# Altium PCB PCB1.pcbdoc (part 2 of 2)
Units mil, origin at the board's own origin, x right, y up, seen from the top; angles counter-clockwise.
Board outline 1771.65 x 1825.33 mil, 2 copper layers (Top Layer, Bottom Layer), stack 62.206 mil thick; 72 components, 46 nets, 229 pads, 305 vias.
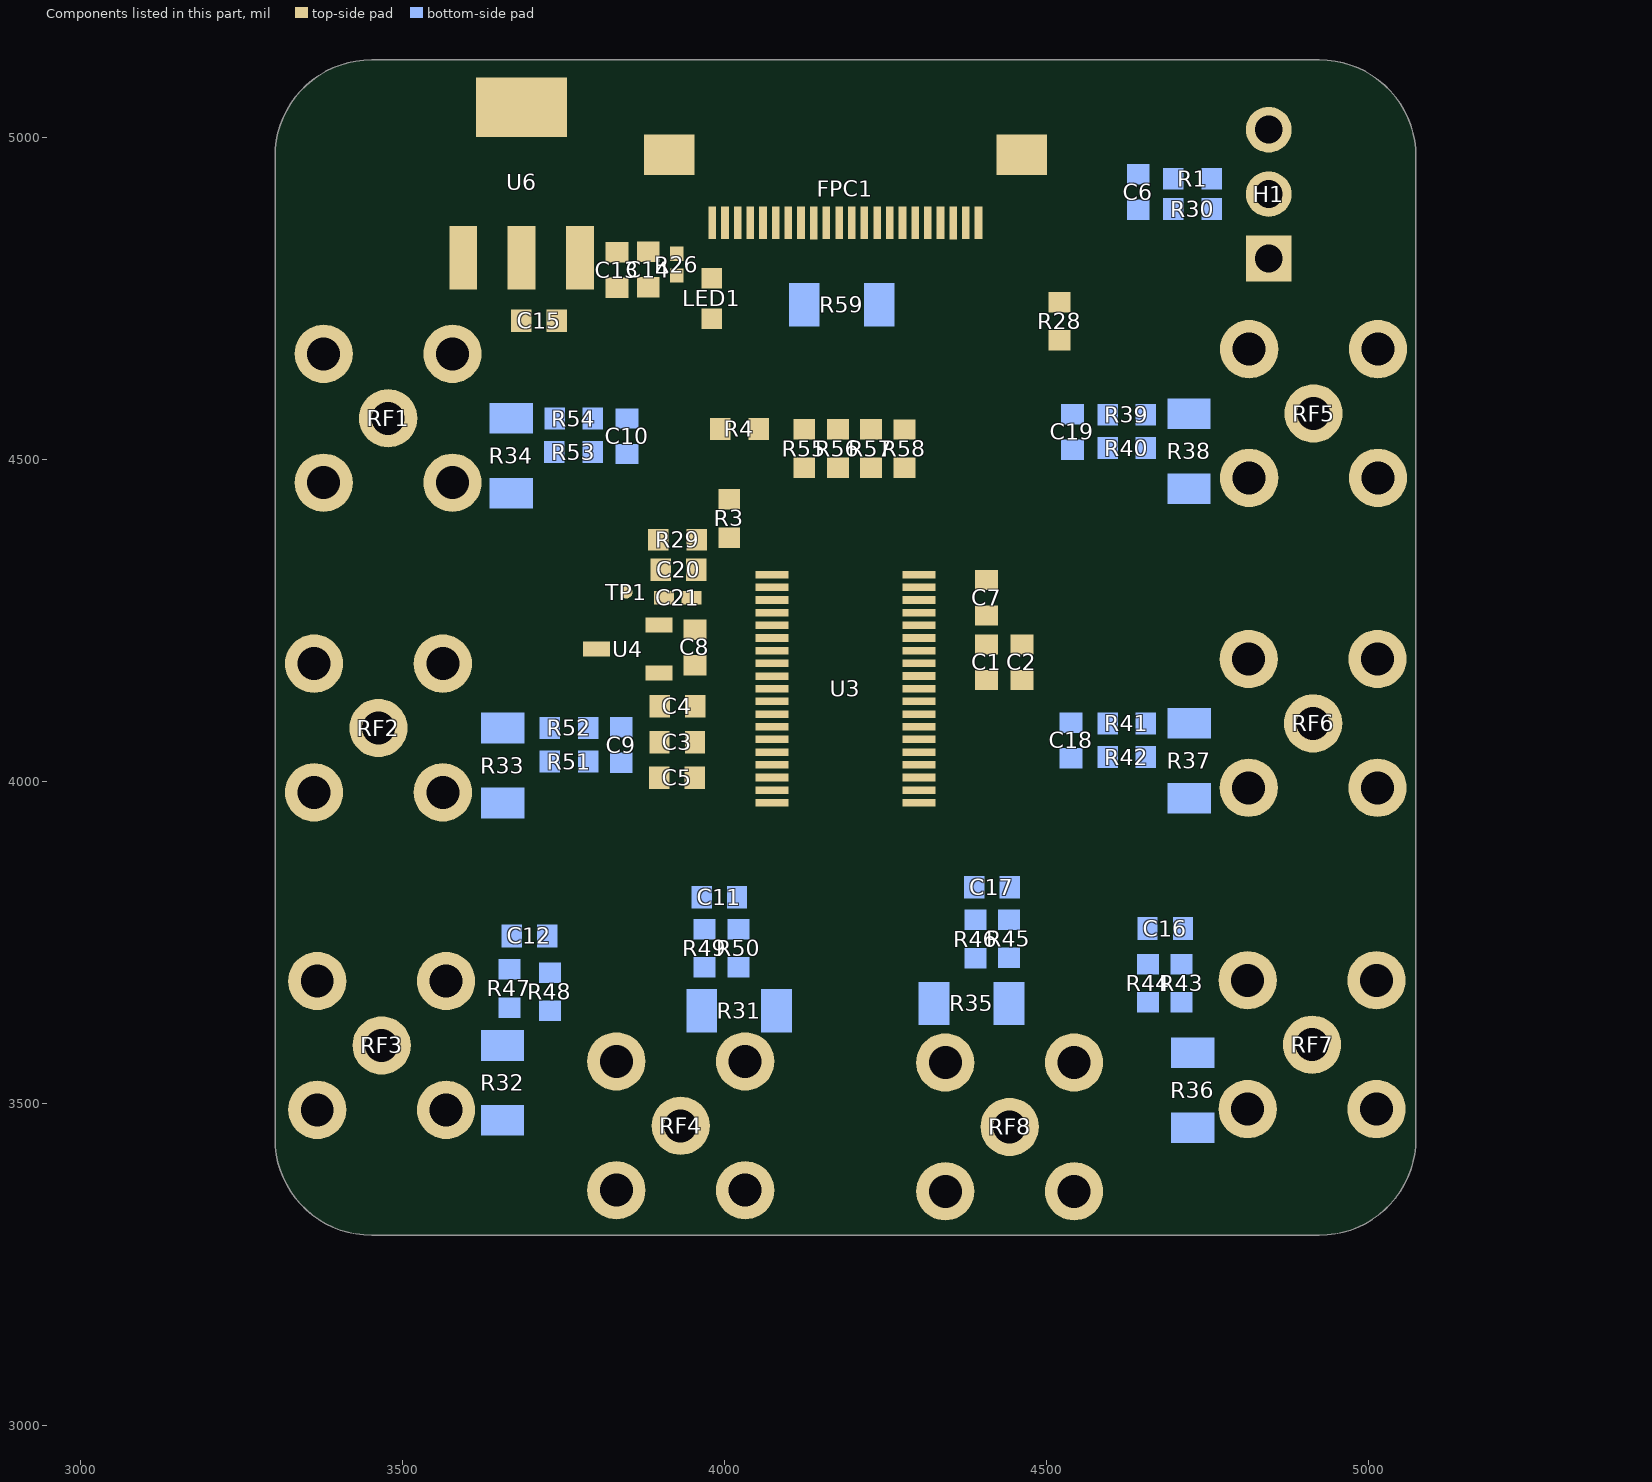
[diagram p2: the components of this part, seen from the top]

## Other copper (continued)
Bottom Layer:
  region net $1N11929: 4621.6,4901.16 4628.74,4908.17 ccw(c4644.65,4929.38) 4644.65,4902.86 4625,4887.15 ccw(c4594.43,4887.15)
  region net $1N11847: 4628.74,4921.18 4621.64,4928.23 ccw(c4594.3,4942.2) 4625,4942.2 4644.65,4926.49 ccw(c4644.65,4899.97)
  region net $1N2508: 3872.77,4088.48 3872.77,4078.48 ccw(c3872.77,4059.73) 3857.77,4070.98 3857.77,4095.98 ccw(c3872.77,4107.23)
  region net $1N2515: 3872.77,4033.36 3872.77,4023.36 ccw(c3872.77,4004.61) 3857.77,4015.86 3857.77,4040.86 ccw(c3872.77,4052.11)
  region net $1N2496: 3872.01,4542.7 3858.57,4542 ccw(c3842.66,4520.79) 3842.66,4547.3 3866.71,4558.61 ccw(c3893.23,4558.61)
  region net $1N2502: 3872.01,4491.98 3862.97,4486.88 ccw(c3847.06,4465.67) 3847.06,4492.18 3866.71,4507.89 ccw(c3893.23,4507.89)
  region net $1N2534: 3975.1,3852.41 3985.1,3852.41 ccw(c4007.52,3837.41) 3980.55,3837.41 3967.6,3837.41 ccw(c3956.35,3852.41)
  region net $1N2549: 4019.61,3852.41 4029.61,3852.41 ccw(c4051.2,3852.41) 4035.67,3837.41 4012.11,3837.41 ccw(c4000.86,3852.41)
  region net $1N2525: 3664.8,3792.41 3674.8,3792.41 ccw(c3693.55,3792.41) 3682.3,3777.41 3657.3,3777.41 ccw(c3646.05,3792.41)
  region net $1N2541: 3755.67,3764.69 3755.67,3754.69 ccw(c3755.67,3735.94) 3740.67,3747.19 3740.67,3772.19 ccw(c3755.67,3783.44)
  region net $1N3142: 4636.23,3770.32 4626.27,3794.42 ccw(c4640.37,3808.52) 4641.53,3788.61 4641.53,3754.41 ccw(c4615.01,3754.41)
  region net $1N3136: 4687.95,3801.13 4706.72,3796.51 ccw(c4728.8,3818.58) 4720.04,3788.61 4696.65,3788.61 ccw(c4657.51,3770.68)
  region net $1N3155: 4382.99,3867.85 4392.99,3867.85 ccw(c4411.74,3867.85) 4400.49,3852.85 4375.49,3852.85 ccw(c4364.24,3867.85)
  region net $1N3148: 4438.53,3867.85 4448.53,3867.85 ccw(c4467.28,3867.85) 4456.03,3852.85 4431.03,3852.85 ccw(c4419.78,3867.85)
  region net $1N17239: 4505.89,4035.09 4505.89,4045.09 ccw(c4505.89,4066.18) 4520.89,4051.36 4520.89,4027.59 ccw(c4505.89,4016.34)
  region net $1N17244: 4505.89,4070.09 4505.89,4080.09 ccw(c4505.89,4098.84) 4520.89,4087.59 4520.89,4074.98 ccw(c4520.89,4049.53)
  region net $1N3111: 4545.63,4483.8 4535.63,4483.8 ccw(c4516.88,4483.8) 4528.13,4498.8 4553.13,4498.8 ccw(c4564.38,4483.8)
  region net $1N3102: 4512.34,4564.67 4512.34,4574.67 ccw(c4512.34,4585.88) 4522.92,4582.17 4522.92,4557.17 ccw(c4512.34,4553.46)
  region net AUX: 4803.6,4844.83 4812.09,4853.31 ccw(c4831.18,4878.77) 4831.18,4846.95 4809.96,4825.74 ccw(c4778.14,4825.74)
  region net AUX: 4779.21,4886.19 4787.73,4860.7 ccw(c4752.44,4825.41) 4772.63,4871.05 4772.63,4905.07 ccw(c4802.99,4905.07)
  region net $1N3616: 3975.64,3591.86 3963.64,3591.86 ccw(c3941.14,3591.86) 3954.64,3609.86 3984.64,3609.86 ccw(c3998.14,3591.86)
  region net $1N3593: 3604.36,3583.52 3604.36,3595.52 ccw(c3604.36,3618.02) 3622.36,3604.52 3622.36,3574.52 ccw(c3604.36,3561.02)
  region net $1N3571: 3604.48,4076.44 3604.48,4088.44 ccw(c3604.48,4110.94) 3622.48,4097.44 3622.48,4067.44 ccw(c3604.48,4053.94)
  region net $1N3547: 3617.74,4557.39 3617.74,4569.39 ccw(c3617.74,4591.89) 3635.74,4578.39 3635.74,4548.39 ccw(c3617.74,4534.89)
  region net $1N20017: 4450.19,3603.42 4438.19,3603.42 ccw(c4415.69,3603.42) 4429.19,3621.42 4459.19,3621.42 ccw(c4472.69,3603.42)
  region net $1N17152: 4775.85,3595.69 4775.85,3585.69 ccw(c4775.85,3566.94) 4760.85,3578.19 4760.85,3601.68 ccw(c4775.85,3617.46)
  region net $1N16947: 4773.47,4095.53 4773.47,4083.53 ccw(c4773.47,4061.03) 4755.47,4074.53 4755.47,4104.53 ccw(c4773.47,4118.03)
  region net $1N16896: 4773.29,4576.78 4773.29,4564.78 ccw(c4773.29,4542.28) 4755.29,4555.78 4755.29,4585.78 ccw(c4773.29,4599.28)
  region net $1N3547: 3539.63,4569.39 3539.63,4557.39 3537.62,4557.15 3535.56,4556.48 3533.46,4555.41 3531.34,4554.01 3529.19,4552.32 3527.05,4550.39 3522.79,4546.03 3518.66,4541.35 3514.75,4536.75 3511.14,4532.64 3507.94,4529.44 3507.94,4597.35 3511.14,4594.14 3514.75,4590.03 3518.66,4585.43 3522.79,4580.75 3527.05,4576.39 3529.19,4574.47 3531.34,4572.78 3533.46,4571.37 3535.56,4570.31 3537.62,4569.63
  region net $1N3571: 3524.63,4088.44 3524.63,4076.44 3522.62,4076.2 3520.56,4075.52 3518.46,4074.45 3516.34,4073.05 3514.19,4071.36 3512.05,4069.43 3507.79,4065.08 3503.66,4060.4 3499.75,4055.8 3496.14,4051.69 3492.94,4048.48 3492.94,4116.39 3496.14,4113.18 3499.75,4109.08 3503.66,4104.48 3507.79,4099.79 3512.05,4095.44 3514.19,4093.51 3516.34,4091.82 3518.46,4090.42 3520.56,4089.35 3522.62,4088.67
  region net $1N3593: 3529.61,3595.52 3529.65,3583.52 3525.99,3583.36 3522.87,3582.89 3520.24,3582.14 3518.01,3581.12 3516.13,3579.85 3514.51,3578.36 3513.1,3576.66 3511.82,3574.78 3509.37,3570.55 3506.62,3565.82 3504.95,3563.33 3503,3560.77 3500.69,3558.17 3497.96,3555.55 3497.92,3623.47 3501.13,3620.26 3504.73,3616.15 3508.65,3611.55 3512.78,3606.87 3517.03,3602.52 3519.18,3600.59 3521.32,3598.9 3523.44,3597.5 3525.54,3596.43 3527.6,3595.76
  region net $1N3616: 3963.64,3541.34 3975.64,3485.42 3975.76,3481.93 3976.03,3478.02 3976.74,3469.47 3977,3465.14 3977.06,3460.98 3976.86,3457.12 3976.29,3453.72 3937.75,3509.64 3940.89,3509.47 3943.82,3509.7 3946.56,3510.31 3949.09,3511.28 3951.41,3512.57 3953.54,3514.17 3955.46,3516.05 3957.18,3518.19 3958.69,3520.55 3960.01,3523.12 3961.12,3525.86 3962.03,3528.75 3962.73,3531.77 3963.24,3534.9 3963.54,3538.09
  region net $1N3616: 3963.64,3541.34 3975.64,3480.11 3975.81,3475.14 3976.21,3470.94 3977.08,3463.9 3977.23,3460.57 3976.97,3457.04 3976.15,3453.07 3974.61,3448.42 3937.75,3509.64 3940.89,3509.47 3943.82,3509.7 3946.56,3510.31 3949.09,3511.28 3951.41,3512.57 3953.54,3514.17 3955.46,3516.05 3957.18,3518.19 3958.69,3520.55 3960.01,3523.12 3961.12,3525.86 3962.03,3528.75 3962.73,3531.77 3963.24,3534.9 3963.54,3538.09
  region net $1N16896: 4853.39,4564.78 4853.39,4576.78 4855.4,4577.02 4857.46,4577.7 4859.56,4578.76 4861.68,4580.17 4863.82,4581.86 4865.97,4583.78 4870.22,4588.14 4874.36,4592.82 4878.27,4597.42 4881.88,4601.53 4885.08,4604.74 4885.08,4536.82 4881.88,4540.03 4878.27,4544.14 4874.36,4548.74 4870.22,4553.42 4865.97,4557.78 4863.82,4559.7 4861.68,4561.4 4859.56,4562.8 4857.46,4563.87 4855.4,4564.54
  region net $1N16947: 4852.74,4083.53 4852.68,4095.53 4856.34,4095.69 4859.46,4096.15 4862.09,4096.91 4864.32,4097.93 4866.2,4099.2 4867.82,4100.69 4869.23,4102.39 4870.51,4104.27 4872.96,4108.5 4875.71,4113.23 4877.38,4115.72 4879.33,4118.28 4881.64,4120.88 4884.37,4123.5 4884.43,4055.58 4881.23,4058.79 4877.62,4062.9 4873.7,4067.49 4869.57,4072.17 4865.32,4076.53 4863.18,4078.45 4861.03,4080.14 4858.91,4081.55 4856.81,4082.61 4854.75,4083.29
  region net $1N17152: 4851.1,3585.69 4851.1,3595.69 4853.17,3595.93 4855.26,3596.64 4857.38,3597.74 4859.51,3599.2 4861.64,3600.95 4863.77,3602.94 4867.97,3607.45 4872.04,3612.3 4875.91,3617.07 4879.52,3621.32 4882.79,3624.65 4882.79,3556.73 4879.52,3560.05 4875.91,3564.31 4872.04,3569.08 4867.97,3573.92 4863.77,3578.44 4861.64,3580.43 4859.51,3582.18 4857.38,3583.64 4855.26,3584.74 4853.17,3585.44
  region net $1N20017: 4438.19,3525.4 4450.19,3523.85 4450.42,3521.82 4451.09,3519.75 4452.14,3517.65 4453.53,3515.53 4455.2,3513.4 4457.1,3511.27 4461.4,3507.06 4466.02,3502.96 4470.56,3499.06 4474.62,3495.43 4477.79,3492.16 4409.89,3493.7 4412.54,3496.36 4415.17,3498.61 4417.76,3500.53 4420.28,3502.19 4425.06,3504.97 4429.35,3507.48 4431.25,3508.8 4432.97,3510.24 4434.48,3511.89 4435.76,3513.8 4436.79,3516.04 4437.55,3518.68 4438.03,3521.77
  region net $1N2508: 3987.27,4077.72 3994.34,4084.79 3995.2,4084.05 3996.19,4083.42 3998.39,4082.5 4000.77,4081.94 4003.11,4081.68 3990.38,4068.94 3990.11,4071.28 3989.55,4073.66 3988.63,4075.87 3988.01,4076.85
  region net $1N11847: 4164.59,4255.33 4174.59,4255.33 4174.68,4254.2 4174.93,4253.06 4175.84,4250.85 4177.12,4248.77 4178.59,4246.93 4160.58,4246.93 4162.05,4248.77 4163.34,4250.85 4164.24,4253.06 4164.5,4254.2
  region net $1N2534: 3985.1,3869.51 3975.1,3869.51 3975.01,3870.65 3974.76,3871.78 3973.85,3874 3972.57,3876.07 3971.1,3877.92 3989.11,3877.92 3987.64,3876.07 3986.36,3874 3985.45,3871.78 3985.19,3870.65
  region net $1N2549: 4029.61,3846.49 4019.61,3850.62 4019.36,3852.83 4018.72,3854.96 4017.81,3857.02 4016.77,3859.02 4034.31,3854.9 4032.58,3853.28 4031.08,3851.15 4030.01,3848.78 4029.71,3847.61
  region net $1N3155: 4365.51,3915.3 4358.44,3908.23 4357.57,3908.97 4356.59,3909.59 4354.38,3910.52 4352.01,3911.08 4349.66,3911.34 4362.4,3924.08 4362.66,3921.73 4363.22,3919.36 4364.14,3917.15 4364.77,3916.17
  region net $1N3148: 4448.53,3869.73 4438.53,3869.73 4438.44,3870.86 4438.19,3872 4437.28,3874.21 4436,3876.29 4434.53,3878.13 4452.54,3878.13 4451.07,3876.29 4449.79,3874.21 4448.88,3872 4448.62,3870.86
  region net $1N3142: 4637.83,3782.86 4630.76,3775.79 4629.89,3776.53 4628.91,3777.15 4626.7,3778.08 4624.33,3778.64 4621.98,3778.9 4634.72,3791.64 4634.99,3789.29 4635.54,3786.92 4636.47,3784.71 4637.09,3783.73
  region net $1N3136: 4700.59,3802.63 4693.52,3795.56 4692.65,3796.3 4691.67,3796.92 4689.46,3797.84 4687.09,3798.4 4684.75,3798.67 4697.48,3811.4 4697.75,3809.06 4698.31,3806.69 4699.23,3804.48 4699.85,3803.5
  region net $1N17244: 4487.02,4080.09 4487.02,4070.09 4485.89,4070 4484.75,4069.75 4482.54,4068.84 4480.46,4067.56 4478.62,4066.09 4478.62,4084.1 4480.46,4082.63 4482.54,4081.35 4484.75,4080.44 4485.89,4080.18
  region net $1N17239: 4502.02,4045.09 4502.02,4035.09 4500.89,4035 4499.75,4034.75 4497.54,4033.84 4495.46,4032.56 4493.62,4031.09 4493.62,4049.1 4495.46,4047.63 4497.54,4046.35 4499.75,4045.44 4500.89,4045.18
  region net $1N2515: 4106.34,4029.96 4099.26,4037.03 4100,4037.9 4100.63,4038.88 4101.55,4041.09 4102.11,4043.46 4102.38,4045.81 4115.11,4033.07 4112.77,4032.81 4110.39,4032.25 4108.18,4031.32 4107.2,4030.7
  region net $1N2525: 3861.01,3929.69 3861.01,3939.69 3862.15,3939.78 3863.28,3940.04 3865.5,3940.94 3867.57,3942.23 3869.42,3943.7 3869.42,3925.69 3867.57,3927.16 3865.5,3928.44 3863.28,3929.35 3862.15,3929.6
  region net $1N2541: 3889.34,3859.6 3882.27,3866.67 3883.01,3867.53 3883.63,3868.52 3884.55,3870.72 3885.11,3873.1 3885.38,3875.44 3898.11,3862.71 3895.77,3862.44 3893.39,3861.88 3891.19,3860.96 3890.2,3860.34
  region net $1N2502: 3997.27,4107.72 4004.34,4114.79 4005.2,4114.05 4006.19,4113.42 4008.39,4112.5 4010.77,4111.94 4013.11,4111.68 4000.38,4098.94 4000.11,4101.28 3999.55,4103.66 3998.63,4105.87 3998.01,4106.85
  region net $1N3102: 4360.39,4129.79 4367.46,4122.72 4366.72,4121.85 4366.09,4120.87 4365.17,4118.66 4364.61,4116.28 4364.35,4113.94 4351.61,4126.68 4353.95,4126.94 4356.33,4127.5 4358.54,4128.42 4359.52,4129.05
  region net $1N3111: 4415.39,4129.79 4422.46,4122.72 4421.72,4121.85 4421.09,4120.87 4420.17,4118.66 4419.61,4116.28 4419.35,4113.94 4406.61,4126.68 4408.95,4126.94 4411.33,4127.5 4413.54,4128.42 4414.52,4129.05
  region net 5V_USB: 4138.71,4171.42 4138.71,4161.42 4137.57,4161.33 4136.44,4161.07 4134.22,4160.17 4132.15,4158.88 4130.3,4157.41 4130.3,4175.42 4132.15,4173.95 4134.22,4172.67 4136.44,4171.76 4137.57,4171.51
  region net 5V_USB: 4107.2,4173.95 4113.85,4181.44 4114.72,4180.7 4115.71,4180.08 4117.95,4179.16 4120.36,4178.63 4122.72,4178.42 4110.41,4165.27 4110.09,4167.6 4109.5,4169.94 4108.57,4172.11 4107.94,4173.08
  region net 5V_USB: 4238.77,4161.42 4233.86,4171.42 4234.97,4171.53 4236.15,4171.83 4238.55,4172.91 4240.7,4174.44 4241.58,4175.3 4242.26,4176.19 4247.17,4158.86 4245.15,4159.8 4243.08,4160.62 4240.96,4161.2
  region net 3.3V: 4254.34,4224.6 4247.27,4231.67 4248.01,4232.53 4248.63,4233.52 4249.55,4235.72 4250.11,4238.1 4250.38,4240.44 4263.11,4227.71 4260.77,4227.44 4258.39,4226.88 4256.19,4225.96 4255.2,4225.34
  region net 5V_USB: 3954.8,4832.28 3947.73,4825.21 3946.86,4825.95 3945.88,4826.58 3943.67,4827.5 3941.3,4828.06 3938.96,4828.32 3951.69,4841.06 3951.96,4838.72 3952.52,4836.34 3953.44,4834.13 3954.06,4833.15
  region net 5V_USB: 3931.68,4825.21 3924.61,4832.28 3925.35,4833.15 3925.98,4834.13 3926.9,4836.34 3927.46,4838.72 3927.72,4841.06 3940.46,4828.32 3938.11,4828.06 3935.74,4827.5 3933.53,4826.58 3932.55,4825.95
  region net 5V_USB: 3783.61,4353.44 3793.61,4353.44 3793.7,4352.33 3793.96,4351.26 3794.86,4349.25 3796.15,4347.39 3797.62,4345.64 3779.61,4345.64 3781.08,4347.39 3782.36,4349.25 3783.27,4351.26 3783.52,4352.33

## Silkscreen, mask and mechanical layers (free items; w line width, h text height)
Bottom Silkscreen Layer:
  lines w10: 3317.36,3474.69 3517.36,3474.69 3517.36,3844.69 3317.36,3844.69 3317.36,3474.69 ; 3317.36,3964.69 3512.36,3964.69 3512.36,4344.69 3317.36,4344.69 3317.36,3964.69 ; 3317.36,4444.69 3512.36,4444.69 3512.36,4809.69 3317.36,4809.69 3317.36,4444.69 ; 3627.36,3309.69 4052.36,3309.69 4052.36,3424.69 3627.36,3424.69 3627.36,3309.69 ; 4112.36,3309.69 4562.36,3309.69 4562.36,3429.69 4112.36,3429.69 4112.36,3309.69 ; 4877.36,4459.69 5057.36,4459.69 5057.36,4769.69 4877.36,4769.69 4877.36,4459.69 ; 4887.36,3474.69 5072.91,3474.69 5072.91,3850.36 4887.36,3850.36 4887.36,3474.69 ; 4887.36,3970.36 5072.91,3970.36 5072.91,4344.69 4887.36,4344.69 4887.36,3970.36
  text "AGND" at 5067.36,4914.69 h78.74
  text "3.3V" at 5057.36,4849.69 h78.74
  text "墨藤" at 3872.36,4799.69 h120
  text "AUX" at 5062.36,4784.69 h78.74
  text "IN6" at 3497.36,4694.69 h120
  text "IN5" at 4992.36,4689.69 h78.74
  text "IN7" at 3497.36,4224.69 h120
  text "IN4" at 5057.36,4224.69 h120
  text "IN3" at 5057.36,3729.69 h120
  text "IN0" at 3492.36,3724.69 h120
  text "IN1" at 3767.36,3304.69 h120
  text "IN2" at 4277.36,3304.69 h120

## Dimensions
3302.36,2804.69 to 5072.36,2804.69 on Document Layer
5722.36,3294.69 to 5722.36,5119.69 on Document Layer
